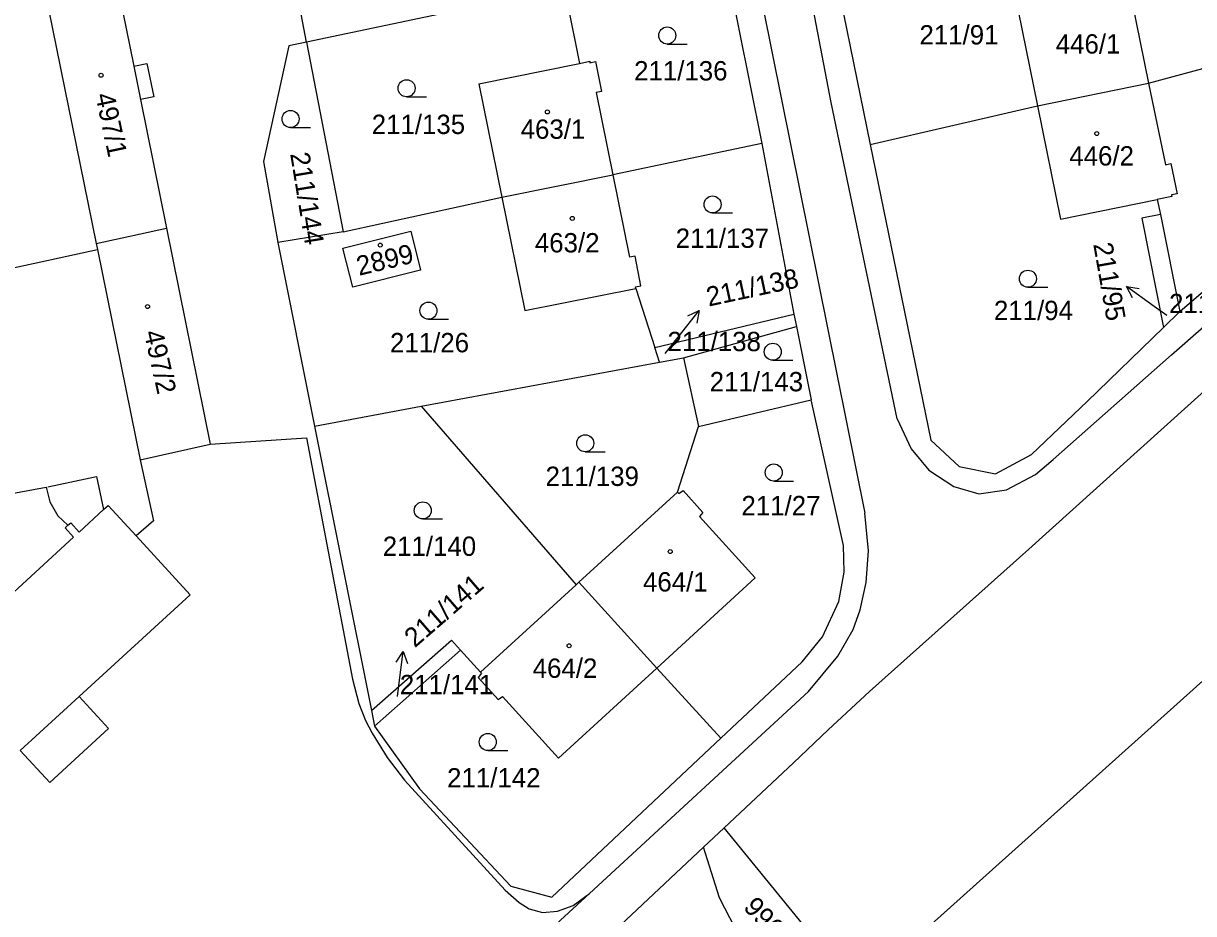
# Model space of a CAD drawing. Extents: x -735249 to -729401, y -1124843 to -1121828.
# Drawn here: x -733187.6 to -733084.7, y -1123571.3 to -1123493 of the extents above; entities that cross this region are included whole.
import ezdxf

# ---------------------------------------------------------------- set-up
doc = ezdxf.new("R2010")
doc.units = 0
for name, color, linetype in [('Vrstva 1', 7, 'Continuous'), ('Vrstva 16', 7, 'Continuous'), ('Vrstva 18', 7, 'Continuous'), ('Vrstva 19', 7, 'Continuous'), ('Vrstva 25', 7, 'Continuous'), ('Vrstva 4', 7, 'Continuous')]:
    doc.layers.add(name, color=color, linetype=linetype)

msp = doc.modelspace()

# ---------------------------------------------------------------- linework, layer by layer
at = {"layer": 'Vrstva 1'}
for points in [[(-733116.55, -1123500), (-733125, -1123455.89)], [(-733162.7, -1123494.69), (-733165.76, -1123478.68)], [(-733125, -1123479.49), (-733113.6, -1123536.1)], [(-733116.65, -1123486.44), (-733113.13, -1123503.68)], [(-733179.53, -1123488.73), (-733177.9, -1123496.81)], [(-733125.74, -1123488.27), (-733122.66, -1123503.59)], [(-733185.75, -1123490.05), (-733181.2, -1123512.41)], [(-733141.76, -1123490.26), (-733162.7, -1123494.69)], [(-733139.78, -1123491.18), (-733138.69, -1123496.56)], [(-733100.43, -1123490.33), (-733098.4, -1123500.3)], [(-733090.1, -1123491.08), (-733088.63, -1123498.3)], [(-733088.63, -1123498.3), (-733073.67, -1123494.26)], [(-733164.27, -1123495.02), (-733166.49, -1123505.2)], [(-733162.7, -1123494.69), (-733164.27, -1123495.02)], [(-733162.7, -1123494.69), (-733159.49, -1123511.38)], [(-733138.69, -1123496.56), (-733137.79, -1123496.38)], [(-733137.79, -1123496.38), (-733137.77, -1123496.5)], [(-733137.77, -1123496.5), (-733137.28, -1123496.4)], [(-733137.28, -1123496.4), (-733136.75, -1123499.02)], [(-733177.9, -1123496.81), (-733176.74, -1123496.57)], [(-733176.74, -1123496.57), (-733176.15, -1123499.49)], [(-733147.54, -1123498.36), (-733138.69, -1123496.56)], [(-733147.54, -1123498.36), (-733145.52, -1123508.33)], [(-733098.4, -1123500.3), (-733088.63, -1123498.3)], [(-733088.63, -1123498.3), (-733087.16, -1123505.47)], [(-733176.15, -1123499.49), (-733177.31, -1123499.73)], [(-733136.75, -1123499.02), (-733137.24, -1123499.12)], [(-733137.24, -1123499.12), (-733135.77, -1123506.36)], [(-733177.31, -1123499.73), (-733175.02, -1123511.04)], [(-733110.74, -1123527.81), (-733116.55, -1123500)], [(-733113.13, -1123503.68), (-733098.4, -1123500.3)], [(-733098.4, -1123500.3), (-733096.37, -1123510.26)], [(-733122.66, -1123503.59), (-733135.77, -1123506.36)], [(-733122.66, -1123503.59), (-733119.83, -1123518.62)], [(-733113.13, -1123503.68), (-733107.79, -1123529.69)], [(-733166.49, -1123505.2), (-733165.22, -1123512.3)], [(-733087.16, -1123505.47), (-733086.67, -1123505.37)], [(-733086.67, -1123505.37), (-733086.13, -1123508.02)], [(-733085.9, -1123518.38), (-733071.06, -1123505.67)], [(-733145.52, -1123508.33), (-733135.77, -1123506.36)], [(-733135.77, -1123506.36), (-733134.3, -1123513.6)], [(-733159.49, -1123511.38), (-733145.52, -1123508.33)], [(-733145.52, -1123508.33), (-733143.49, -1123518.3)], [(-733096.37, -1123510.26), (-733087.87, -1123508.53)], [(-733086.59, -1123508.27), (-733087.87, -1123508.53)], [(-733087.87, -1123508.53), (-733087.6, -1123509.85)], [(-733086.13, -1123508.02), (-733086.62, -1123508.12)], [(-733086.62, -1123508.12), (-733086.59, -1123508.27)], [(-733087.6, -1123509.85), (-733089.22, -1123510.18)], [(-733089.22, -1123510.18), (-733087.33, -1123519.78)], [(-733087.6, -1123509.85), (-733085.9, -1123518.38)], [(-733181.2, -1123512.41), (-733175.02, -1123511.04)], [(-733175.02, -1123511.04), (-733171.18, -1123530.04)], [(-733159.49, -1123511.38), (-733165.22, -1123512.3)], [(-733159.5, -1123512.82), (-733153.54, -1123511.31)], [(-733153.54, -1123511.31), (-733152.67, -1123514.74)], [(-733181.2, -1123512.41), (-733181.09, -1123512.93)], [(-733165.22, -1123512.3), (-733162.01, -1123528.44)], [(-733158.64, -1123516.24), (-733159.5, -1123512.82)], [(-733181.09, -1123512.93), (-733177.34, -1123531.4)], [(-733133.81, -1123513.5), (-733134.3, -1123513.6)], [(-733133.29, -1123516.12), (-733133.81, -1123513.5)], [(-733152.67, -1123514.74), (-733158.64, -1123516.24)], [(-733086.62, -1123522.18), (-733078.56, -1123515.13)], [(-733143.49, -1123518.3), (-733133.74, -1123516.35)], [(-733133.77, -1123516.21), (-733133.29, -1123516.12)], [(-733133.74, -1123516.35), (-733133.77, -1123516.21)], [(-733133.74, -1123516.35), (-733132.07, -1123521.53)], [(-733132.07, -1123521.53), (-733119.83, -1123518.62)], [(-733119.83, -1123518.62), (-733119.61, -1123519.7)], [(-733087.33, -1123519.78), (-733085.9, -1123518.38)], [(-733129.54, -1123522.45), (-733119.61, -1123519.7)], [(-733119.61, -1123519.7), (-733118.32, -1123526.15)], [(-733049.16, -1123519.71), (-733112.61, -1123576.59)], [(-733094.03, -1123526.3), (-733087.33, -1123519.78)], [(-733131.65, -1123522.84), (-733132.07, -1123521.53)], [(-733152.61, -1123526.71), (-733131.65, -1123522.84)], [(-733131.65, -1123522.84), (-733129.54, -1123522.45)], [(-733129.54, -1123522.45), (-733128.23, -1123528.47)], [(-733097.03, -1123531.38), (-733086.62, -1123522.18)], [(-733099.16, -1123539.28), (-733083.11, -1123524.8)], [(-733128.23, -1123528.47), (-733118.32, -1123526.15)], [(-733115.47, -1123538.95), (-733118.32, -1123526.15)], [(-733162.01, -1123528.44), (-733152.61, -1123526.71)], [(-733152.61, -1123526.71), (-733138.98, -1123542.39)], [(-733098.92, -1123530.94), (-733094.03, -1123526.3)], [(-733110.74, -1123527.81), (-733109.53, -1123530.44)], [(-733162.01, -1123528.44), (-733157, -1123553.46)], [(-733130.07, -1123534.27), (-733128.23, -1123528.47)], [(-733177.34, -1123531.4), (-733171.18, -1123530.04)], [(-733171.18, -1123530.04), (-733162.72, -1123529.49)], [(-733162.72, -1123529.49), (-733158.67, -1123550.69)], [(-733107.79, -1123529.69), (-733105.3, -1123532)], [(-733109.53, -1123530.44), (-733107.97, -1123532.33)], [(-733102.11, -1123532.65), (-733098.92, -1123530.94)], [(-733098.59, -1123532.71), (-733097.03, -1123531.38)], [(-733107.97, -1123532.33), (-733105.78, -1123533.77)], [(-733105.3, -1123532), (-733102.11, -1123532.65)], [(-733101.14, -1123534.05), (-733098.59, -1123532.71)], [(-733188.95, -1123534.42), (-733185.62, -1123533.82)], [(-733185.62, -1123533.82), (-733185.28, -1123535.12)], [(-733138.74, -1123542.18), (-733130.07, -1123534.27)], [(-733130.07, -1123534.27), (-733129.97, -1123534.38)], [(-733129.97, -1123534.38), (-733129.58, -1123534.11)], [(-733129.58, -1123534.11), (-733127.84, -1123536.03)], [(-733105.78, -1123533.77), (-733103.56, -1123534.39)], [(-733103.56, -1123534.39), (-733101.14, -1123534.05)], [(-733185.28, -1123535.12), (-733184.59, -1123536.33)], [(-733184.59, -1123536.33), (-733183.7, -1123537.17)], [(-733127.84, -1123536.03), (-733128.15, -1123536.39)], [(-733128.15, -1123536.39), (-733123.24, -1123541.79)], [(-733113.28, -1123539.42), (-733113.6, -1123536.1)], [(-733183.95, -1123537.4), (-733183.7, -1123537.17)], [(-733183.2, -1123538.21), (-733183.95, -1123537.4)], [(-733189.98, -1123544.42), (-733183.2, -1123538.21)], [(-733115.4, -1123541.3), (-733115.47, -1123538.95)], [(-733113.49, -1123542.21), (-733113.28, -1123539.42)], [(-733113.17, -1123551.77), (-733099.16, -1123539.28)], [(-733115.87, -1123543.87), (-733115.4, -1123541.3)], [(-733147.4, -1123550.08), (-733138.98, -1123542.39)], [(-733138.98, -1123542.39), (-733138.74, -1123542.18)], [(-733138.74, -1123542.18), (-733131.89, -1123549.72)], [(-733131.89, -1123549.72), (-733123.24, -1123541.79)], [(-733114.01, -1123544.6), (-733113.49, -1123542.21)], [(-733117.31, -1123546.97), (-733115.87, -1123543.87)], [(-733114.63, -1123546.32), (-733114.01, -1123544.6)], [(-733115.96, -1123548.67), (-733114.63, -1123546.32)], [(-733157, -1123553.46), (-733149.96, -1123547.26)], [(-733149.96, -1123547.26), (-733149.15, -1123548.15)], [(-733119.1, -1123549.16), (-733117.31, -1123546.97)], [(-733149.15, -1123548.15), (-733156.72, -1123554.84)], [(-733149.15, -1123548.15), (-733147.4, -1123550.08)], [(-733118.56, -1123551.79), (-733115.96, -1123548.67)], [(-733140.54, -1123557.65), (-733131.89, -1123549.72)], [(-733131.89, -1123549.72), (-733126.26, -1123555.89)], [(-733126.26, -1123555.89), (-733119.1, -1123549.16)], [(-733158.67, -1123550.69), (-733158.1, -1123552.85)], [(-733147.31, -1123550.18), (-733147.62, -1123550.54)], [(-733147.62, -1123550.54), (-733145.86, -1123552.49)], [(-733147.4, -1123550.08), (-733147.31, -1123550.18)], [(-733137.81, -1123569.53), (-733118.56, -1123551.79)], [(-733116.83, -1123555.14), (-733113.17, -1123551.77)], [(-733158.1, -1123552.85), (-733157.53, -1123554.32)], [(-733145.86, -1123552.49), (-733145.47, -1123552.21)], [(-733145.47, -1123552.21), (-733140.54, -1123557.65)], [(-733157, -1123553.46), (-733156.72, -1123554.84)], [(-733157.53, -1123554.32), (-733156.93, -1123555.43)], [(-733156.72, -1123554.84), (-733152.76, -1123560.34)], [(-733156.93, -1123555.43), (-733155.61, -1123557.59)], [(-733141.13, -1123569.87), (-733126.26, -1123555.89)], [(-733119.87, -1123558.04), (-733116.83, -1123555.14)], [(-733155.61, -1123557.59), (-733154.08, -1123559.58)], [(-733125.98, -1123563.77), (-733119.87, -1123558.04)], [(-733154.08, -1123559.58), (-733145.23, -1123569.25)], [(-733152.76, -1123560.34), (-733144.72, -1123568.9)], [(-733127.8, -1123565.48), (-733125.98, -1123563.77)], [(-733114.28, -1123578.09), (-733125.98, -1123563.77)], [(-733136.55, -1123573.69), (-733127.8, -1123565.48)], [(-733126.37, -1123569.93), (-733127.8, -1123565.48)], [(-733145.23, -1123569.25), (-733144.01, -1123570.32)], [(-733144.72, -1123568.9), (-733141.13, -1123569.87)], [(-733195.46, -1123622.51), (-733137.81, -1123569.53)], [(-733144.01, -1123570.32), (-733143.12, -1123570.88)], [(-733139.26, -1123570.58), (-733137.81, -1123569.53)], [(-733124.99, -1123572.6), (-733126.37, -1123569.93)], [(-733143.12, -1123570.88), (-733141.96, -1123571.21)], [(-733141.96, -1123571.21), (-733140.64, -1123571.1)], [(-733140.64, -1123571.1), (-733139.26, -1123570.58)]]:
    msp.add_lwpolyline(points, dxfattribs=at)
at = {"layer": 'Vrstva 16'}
for points in [[(-733087.03, -1123518.72), (-733088.13, -1123517.93)], [(-733131.15, -1123522.06), (-733130.02, -1123520.64)], [(-733154.7, -1123552.22), (-733154.58, -1123551.25)]]:
    msp.add_lwpolyline(points, dxfattribs=at)
at = {"layer": 'Vrstva 25'}
for points in [[(-733130.97, -1123494.86), (-733129.22, -1123494.86)], [(-733153.9, -1123499.5), (-733152.15, -1123499.5)], [(-733164.11, -1123502.2), (-733162.36, -1123502.2)], [(-733126.99, -1123509.71), (-733125.24, -1123509.71)], [(-733099.25, -1123516.24), (-733097.5, -1123516.24)], [(-733088.13, -1123517.93), (-733090.569, -1123516.184)], [(-733090.047, -1123517.173), (-733090.569, -1123516.184), (-733089.465, -1123516.36)], [(-733151.98, -1123519.05), (-733150.23, -1123519.05)], [(-733130.02, -1123520.64), (-733128.153, -1123518.293)], [(-733129.167, -1123518.764), (-733128.153, -1123518.293), (-733128.384, -1123519.387)], [(-733121.69, -1123522.66), (-733119.94, -1123522.66)], [(-733138.19, -1123530.71), (-733136.44, -1123530.71)], [(-733121.61, -1123533.28), (-733119.86, -1123533.28)], [(-733152.48, -1123536.61), (-733150.73, -1123536.61)], [(-733154.821, -1123549.203), (-733154.199, -1123548.275), (-733153.83, -1123549.33)], [(-733154.58, -1123551.25), (-733154.199, -1123548.275)], [(-733146.76, -1123556.97), (-733145.01, -1123556.97)]]:
    msp.add_lwpolyline(points, dxfattribs=at)
for centre, radius in [((-733130.97, -1123494.11), 0.75), ((-733180.78, -1123497.61), 0.175), ((-733153.9, -1123498.75), 0.75), ((-733164.11, -1123501.45), 0.75), ((-733141.52, -1123500.83), 0.175), ((-733093.19, -1123502.73), 0.175), ((-733126.99, -1123508.96), 0.75), ((-733139.33, -1123510.19), 0.175), ((-733156.22, -1123512.54), 0.175), ((-733099.25, -1123515.49), 0.75), ((-733176.69, -1123517.94), 0.175), ((-733151.98, -1123518.3), 0.75), ((-733121.69, -1123521.91), 0.75), ((-733138.19, -1123529.96), 0.75), ((-733121.61, -1123532.53), 0.75), ((-733152.48, -1123535.86), 0.75), ((-733130.71, -1123539.48), 0.175), ((-733139.61, -1123547.76), 0.175), ((-733146.76, -1123556.22), 0.75)]:
    msp.add_circle(centre, radius, dxfattribs=at)
at = {"layer": 'Vrstva 4'}
for points in [[(-733177.9, -1123496.81), (-733177.31, -1123499.73)], [(-733189.45, -1123514.74), (-733181.09, -1123512.93)], [(-733177.34, -1123531.4), (-733176.18, -1123536.79)], [(-733185.47, -1123533.79), (-733181.17, -1123532.89)], [(-733181.17, -1123532.89), (-733180.56, -1123535.79)], [(-733180.56, -1123535.79), (-733180.15, -1123535.42)], [(-733180.15, -1123535.42), (-733177.69, -1123538.11)], [(-733182.71, -1123537.76), (-733180.56, -1123535.79)], [(-733183.7, -1123537.17), (-733183.45, -1123536.94)], [(-733183.45, -1123536.94), (-733182.71, -1123537.76)], [(-733176.18, -1123536.79), (-733177.69, -1123538.11)], [(-733177.69, -1123538.11), (-733172.95, -1123543.29)], [(-733182.71, -1123552.22), (-733172.95, -1123543.29)], [(-733187.89, -1123556.96), (-733182.71, -1123552.22)], [(-733182.71, -1123552.22), (-733180.12, -1123555.03)], [(-733185.28, -1123559.77), (-733180.12, -1123555.03)], [(-733187.89, -1123556.96), (-733185.28, -1123559.77)]]:
    msp.add_lwpolyline(points, dxfattribs=at)

# ---------------------------------------------------------------- texts
at = {"layer": 'Vrstva 16'}
for s, rotation, p in [('211/95', 280.00223, (-733093.508, -1123512.455)), ('211/138', 12.1001, (-733127.337, -1123517.943)), ('211/141', 41.00033, (-733153.181, -1123547.988))]:
    msp.add_text(s, height=1.7, rotation=rotation, dxfattribs=at).set_placement(p)
at = {"layer": 'Vrstva 18'}
for s, p in [('211/91', (-733108.79, -1123494.9)), ('211/136', (-733133.89, -1123498.06)), ('211/135', (-733156.97, -1123502.77)), ('211/137', (-733130.23, -1123512.78)), ('211/95', (-733086.83, -1123518.52)), ('211/94', (-733102.24, -1123519.13)), ('211/138', (-733130.95, -1123521.86)), ('211/26', (-733155.36, -1123521.96)), ('211/143', (-733127.24, -1123525.39)), ('211/139', (-733141.68, -1123533.71)), ('211/27', (-733124.45, -1123536.29)), ('211/140', (-733156, -1123539.86)), ('211/141', (-733154.5, -1123552.02)), ('211/142', (-733150.34, -1123560.22))]:
    msp.add_text(s, height=1.7, dxfattribs=at).set_placement(p)
for s, rotation, p in [('211/144', 279.30222, (-733164.151, -1123504.505)), ('996/1', 313.00249, (-733124.358, -1123570.819))]:
    msp.add_text(s, height=1.7, rotation=rotation, dxfattribs=at).set_placement(p)
at = {"layer": 'Vrstva 19'}
for s, p in [('446/1', (-733096.8, -1123495.7)), ('463/1', (-733143.87, -1123503.19)), ('446/2', (-733095.61, -1123505.54)), ('463/2', (-733142.62, -1123513.18)), ('464/1', (-733133.11, -1123542.99)), ('464/2', (-733142.81, -1123550.58))]:
    msp.add_text(s, height=1.7, dxfattribs=at).set_placement(p)
for s, rotation, p in [('497/1', 281.90224, (-733181.294, -1123499.334)), ('2899', 13.50011, (-733158.083, -1123515.239)), ('497/2', 282.50225, (-733177.022, -1123520.201))]:
    msp.add_text(s, height=1.7, rotation=rotation, dxfattribs=at).set_placement(p)

doc.saveas('drawing.dxf')
